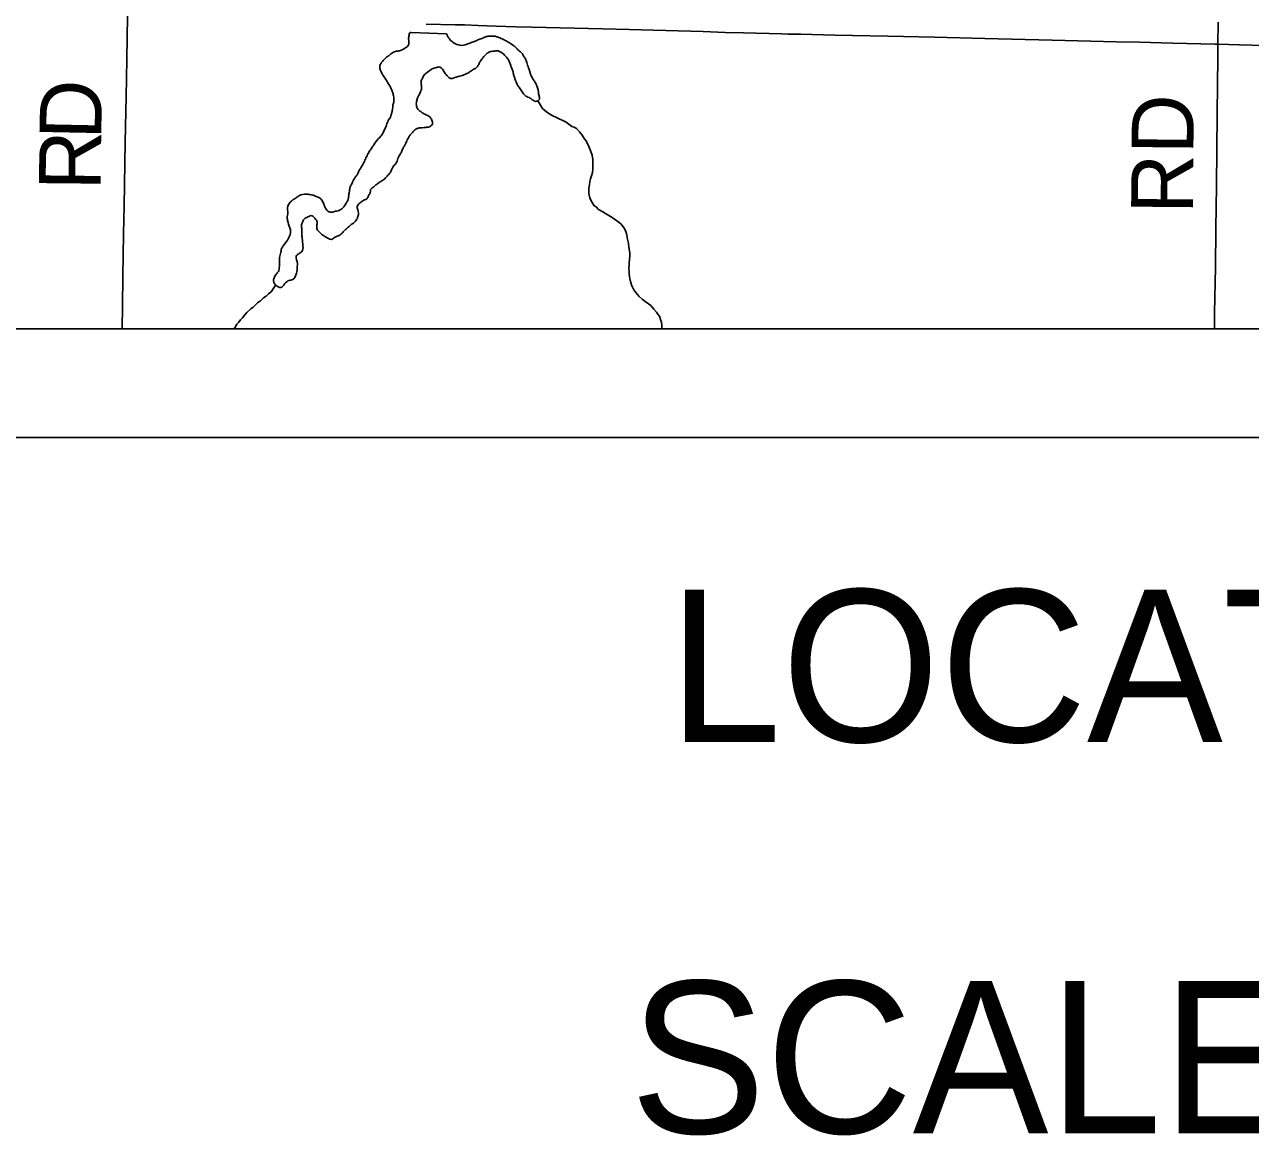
# Model space of a CAD drawing. Extents: x 0 to 34, y 0 to 22.
# Drawn here: x 25.659 to 26.787, y 13.358 to 14.38 of the extents above; entities that cross this region are included whole.
import ezdxf

# ---------------------------------------------------------------- set-up
doc = ezdxf.new("R2010")
doc.units = 0
for name, color, linetype in [('GM_X_County_Road', 7, 'Continuous'), ('GM_X_County_Road_Text', 7, 'Continuous'), ('GM_X_Minor_Lake', 7, 'Continuous'), ('GM_X_Minor_River', 7, 'Continuous'), ('GM_X_Township_Road', 7, 'Continuous'), ('SH_Data', 7, 'Continuous'), ('SH_Text', 7, 'Continuous')]:
    doc.layers.add(name, color=color, linetype=linetype)

msp = doc.modelspace()

# ---------------------------------------------------------------- linework, layer by layer
at = {"layer": 'GM_X_County_Road'}
for points in [[(25.7492, 14.1), (25.7496, 14.1206), (25.75, 14.1479), (25.7505, 14.1871), (25.7511, 14.2131), (25.7519, 14.2716), (25.7522, 14.2853), (25.7525, 14.3002), (25.7528, 14.3132), (25.7535, 14.3474), (25.7541, 14.3873)], [(26.7567, 14.3615), (26.7568, 14.3819)], [(26.7534, 14.1), (26.7536, 14.1147), (26.7543, 14.1563), (26.7548, 14.1917), (26.7553, 14.2315), (26.7559, 14.298), (26.7566, 14.3496), (26.7567, 14.3615)]]:
    msp.add_lwpolyline(points, dxfattribs=at)
at = {"layer": 'GM_X_Minor_Lake'}
msp.add_line((26.0475, 14.3712), (26.0148, 14.3725), dxfattribs=at)
for points in [[(26.0148, 14.3725), (26.0146, 14.3725), (26.013, 14.3699), (26.0126, 14.3664), (26.0129, 14.363), (26.0116, 14.3596), (26.0078, 14.3571), (26.0043, 14.3556), (26.0005, 14.355), (25.997, 14.3532), (25.9943, 14.351), (25.9916, 14.3491), (25.9892, 14.3465), (25.9869, 14.3436), (25.986, 14.3402), (25.9871, 14.3367), (25.9889, 14.3333), (25.9925, 14.3278), (25.9944, 14.3247), (25.9973, 14.3193), (25.9983, 14.3159), (25.999, 14.3121), (25.9989, 14.3083), (25.998, 14.3049), (25.9979, 14.3022), (25.9971, 14.2988), (25.9963, 14.2958), (25.9939, 14.2913), (25.9922, 14.2872), (25.991, 14.2842), (25.9894, 14.2808), (25.9874, 14.2774), (25.9847, 14.2745), (25.9807, 14.2692), (25.9787, 14.2663), (25.9764, 14.2629), (25.9744, 14.2591), (25.9724, 14.255), (25.9703, 14.2505), (25.9676, 14.2464), (25.9663, 14.2434), (25.9648, 14.2408), (25.9628, 14.2382), (25.9608, 14.234), (25.9592, 14.2311), (25.9583, 14.2277), (25.9579, 14.225), (25.9574, 14.2216), (25.9569, 14.2186), (25.9553, 14.2156), (25.953, 14.2122), (25.9491, 14.2089), (25.9464, 14.2082), (25.9426, 14.2072)], [(26.014, 14.2782), (26.0164, 14.2808), (26.0191, 14.2834), (26.0218, 14.2845), (26.0252, 14.2848), (26.0283, 14.2851), (26.0317, 14.2857), (26.0345, 14.2883), (26.0338, 14.2918), (26.0323, 14.2945), (26.0294, 14.2964), (26.0267, 14.2977), (26.0237, 14.2996), (26.0211, 14.302), (26.0197, 14.3054), (26.0198, 14.3081), (26.0206, 14.3115), (26.0218, 14.3141), (26.0234, 14.3175), (26.0243, 14.3201), (26.0244, 14.3236), (26.0241, 14.327), (26.0253, 14.3304), (26.0273, 14.3337), (26.03, 14.3359), (26.0343, 14.3389), (26.0381, 14.3403), (26.0412, 14.3406), (26.0438, 14.3386), (26.0456, 14.3355), (26.0486, 14.332), (26.0512, 14.3301), (26.0542, 14.3307), (26.0581, 14.3318), (26.0607, 14.3325), (26.0661, 14.3346), (26.0696, 14.3368), (26.0723, 14.3386), (26.0754, 14.3404), (26.077, 14.3431), (26.0786, 14.3461), (26.0806, 14.3487), (26.0829, 14.3516), (26.0856, 14.3538), (26.0883, 14.3549), (26.091, 14.3552), (26.0948, 14.3555), (26.0974, 14.3543), (26.1001, 14.3523), (26.1026, 14.3496), (26.1048, 14.3465), (26.107, 14.3404), (26.1084, 14.3369), (26.1091, 14.3335), (26.1101, 14.3304), (26.1112, 14.3277), (26.1123, 14.3246), (26.1145, 14.3215), (26.1196, 14.3145), (26.1233, 14.3125), (26.1263, 14.3106), (26.1293, 14.309), (26.1328, 14.3112), (26.1325, 14.3142), (26.1319, 14.318), (26.1312, 14.3215), (26.1298, 14.3249), (26.1283, 14.3276), (26.1265, 14.3303), (26.125, 14.3334), (26.124, 14.3365), (26.1229, 14.3399), (26.1212, 14.3449), (26.1201, 14.348), (26.1183, 14.3507), (26.1168, 14.3534), (26.1138, 14.3557), (26.1109, 14.3589), (26.1083, 14.3608), (26.1042, 14.3636), (26.1004, 14.3656), (26.0978, 14.3668), (26.0948, 14.368), (26.0921, 14.3689), (26.0887, 14.369), (26.0857, 14.369), (26.0826, 14.368), (26.0791, 14.3666), (26.0753, 14.3651), (26.0711, 14.3634), (26.068, 14.3623), (26.0645, 14.3609), (26.0584, 14.361), (26.0532, 14.3635), (26.0506, 14.3658), (26.0488, 14.3685), (26.0475, 14.3712)], [(25.9426, 14.2072), (25.9392, 14.2076), (25.9362, 14.2108), (25.9351, 14.2135), (25.9333, 14.2173), (25.9307, 14.2204), (25.9277, 14.2216), (25.9243, 14.2229), (25.9217, 14.2233), (25.9183, 14.2238), (25.9122, 14.2224), (25.9094, 14.2206), (25.9063, 14.2184), (25.9036, 14.2162), (25.9016, 14.2128), (25.9014, 14.2056), (25.901, 14.203), (25.9013, 14.1995), (25.9034, 14.1926), (25.9041, 14.1892), (25.9036, 14.1866), (25.8976, 14.1765), (25.8957, 14.1735), (25.8952, 14.1704), (25.8944, 14.1678), (25.8939, 14.1633), (25.8937, 14.156), (25.8932, 14.1534), (25.8913, 14.1508), (25.8893, 14.1474), (25.8884, 14.1444), (25.8891, 14.1417), (25.8917, 14.139), (25.8951, 14.1378), (25.8986, 14.1411), (25.9029, 14.1444), (25.9059, 14.1451), (25.9083, 14.1477), (25.9095, 14.151), (25.91, 14.1537), (25.9101, 14.1571), (25.9105, 14.1598), (25.9092, 14.1666), (25.9119, 14.1692), (25.915, 14.1718), (25.9155, 14.1745), (25.9149, 14.1813), (25.9146, 14.1844), (25.9143, 14.1878), (25.9144, 14.1912), (25.9141, 14.1946), (25.9149, 14.198), (25.9165, 14.2006), (25.92, 14.2028), (25.9238, 14.2039), (25.9264, 14.2015), (25.9286, 14.198), (25.9282, 14.1946), (25.9285, 14.1912), (25.931, 14.1885), (25.9336, 14.1861), (25.9363, 14.1845), (25.9415, 14.1821), (25.9442, 14.1836), (25.9469, 14.185), (25.9504, 14.1868), (25.9531, 14.1898), (25.9562, 14.1924), (25.9598, 14.1957), (25.9625, 14.1975), (25.9648, 14.2005), (25.966, 14.2031), (25.9665, 14.2065), (25.9658, 14.2092), (25.9655, 14.213), (25.9679, 14.2156), (25.9714, 14.2182), (25.9741, 14.2193), (25.9757, 14.2222), (25.9773, 14.2252), (25.9777, 14.2279), (25.9805, 14.2305), (25.9832, 14.2327), (25.9863, 14.2349), (25.9898, 14.2371), (25.9929, 14.2404), (25.9956, 14.2434), (25.9981, 14.2486), (26.0008, 14.252), (26.0028, 14.2565), (26.004, 14.2591), (26.0056, 14.2617), (26.0072, 14.2655), (26.0088, 14.2681), (26.0104, 14.2715), (26.0125, 14.2756), (26.014, 14.2782)]]:
    msp.add_spline(points, degree=3, dxfattribs=at)
at = {"layer": 'GM_X_Minor_River'}
for points in [[(26.1312, 14.3101), (26.1357, 14.3025), (26.1395, 14.2994), (26.1424, 14.2974), (26.1451, 14.2957), (26.1484, 14.2941), (26.1574, 14.29), (26.16, 14.288), (26.1626, 14.286), (26.1649, 14.2852), (26.1668, 14.284), (26.1697, 14.2809), (26.1723, 14.2781), (26.1741, 14.275), (26.1756, 14.273), (26.1777, 14.2692), (26.1788, 14.2661), (26.1802, 14.263), (26.1812, 14.2595), (26.1819, 14.2557), (26.1821, 14.2511), (26.1819, 14.2466), (26.1815, 14.2436), (26.1806, 14.2405), (26.1798, 14.2379), (26.1793, 14.2353), (26.1788, 14.2322), (26.1783, 14.2292), (26.1782, 14.2243), (26.1792, 14.2204), (26.1803, 14.2177), (26.1832, 14.2131), (26.185, 14.2119), (26.1872, 14.2095), (26.191, 14.2075), (26.1951, 14.2051), (26.1996, 14.2023), (26.204, 14.1991), (26.2078, 14.1963), (26.21, 14.1935), (26.2118, 14.1908), (26.2128, 14.1874), (26.2138, 14.1824), (26.2148, 14.1785), (26.2151, 14.1751), (26.2157, 14.1717), (26.216, 14.1694), (26.216, 14.1671), (26.2154, 14.1603), (26.2153, 14.1584), (26.2152, 14.1557), (26.2155, 14.1526), (26.2154, 14.15), (26.2157, 14.1481), (26.2161, 14.1462), (26.2167, 14.1435), (26.2177, 14.1393), (26.2195, 14.1358), (26.2214, 14.1334), (26.2247, 14.1295), (26.2273, 14.1271), (26.2302, 14.1251), (26.2332, 14.1228), (26.2354, 14.1212), (26.238, 14.118), (26.2406, 14.1153), (26.2417, 14.1134), (26.2431, 14.1114), (26.2442, 14.1083), (26.2452, 14.106), (26.2455, 14.1033), (26.2455, 14.1007), (26.2455, 14.1)], [(25.8905, 14.1403), (25.8862, 14.1338), (25.8839, 14.132), (25.8815, 14.1298), (25.8792, 14.1284), (25.8761, 14.1254), (25.8741, 14.124), (25.8722, 14.1221), (25.8698, 14.1199), (25.8675, 14.1181), (25.8639, 14.1148), (25.8619, 14.1126), (25.86, 14.11), (25.858, 14.1081), (25.8564, 14.1059), (25.8548, 14.1041), (25.8528, 14.1007), (25.8523, 14.1)]]:
    msp.add_lwpolyline(points, dxfattribs=at)
at = {"layer": 'GM_X_Township_Road'}
for points in [[(23.5167, 18.4074), (23.5167, 14.1), (28.7673, 14.1), (28.7709, 14.3107), (28.7934, 15.3155), (28.8021, 16.3696)], [(26.0287, 14.3801), (26.0554, 14.3795), (26.0641, 14.3793), (26.0765, 14.3788), (26.0845, 14.3785), (26.0932, 14.3782), (26.1113, 14.3776), (26.1262, 14.3774), (26.1519, 14.3767), (26.1911, 14.3756), (26.2154, 14.3751), (26.249, 14.3743), (26.2834, 14.3732), (26.3036, 14.3725), (26.3204, 14.372), (26.3557, 14.371), (26.3613, 14.3709), (26.3731, 14.3707), (26.4044, 14.37), (26.4533, 14.369), (26.4962, 14.368), (26.5422, 14.3669), (26.6043, 14.3654), (26.6634, 14.3639), (26.6845, 14.3634), (26.715, 14.3627), (26.7541, 14.3616), (26.7567, 14.3615)], [(26.7567, 14.3615), (26.7765, 14.3611), (26.7995, 14.3604), (26.8772, 14.3583), (26.9319, 14.3569), (27.0114, 14.3549), (27.0574, 14.354), (27.1463, 14.3523), (27.1923, 14.3514), (27.2526, 14.3503), (27.2595, 14.3502)]]:
    msp.add_lwpolyline(points, dxfattribs=at)
at = {"layer": 'SH_Data'}
for points in [[(23.4167, 21), (30.4167, 21), (30.4167, 14), (23.4167, 14)], [(23.5167, 20.9), (30.3167, 20.9), (30.3167, 14.1), (23.5167, 14.1)]]:
    msp.add_lwpolyline(points, close=True, dxfattribs=at)

# ---------------------------------------------------------------- texts
at = {"layer": 'GM_X_County_Road_Text'}
for s, height, rotation, p in [('D', 0.0568, 88.8597, (25.7299, 14.2736)), ('RD', 0.05682, 89.5063, (26.7336, 14.2055)), ('R', 0.0568, 89.4399, (25.7295, 14.2271))]:
    msp.add_text(s, height=height, rotation=rotation, dxfattribs=at).set_placement(p)
at = {"layer": 'SH_Text'}
for s, p in [('LOCATION MAP', (26.2513, 13.72)), ('SCALE IN MILES', (26.216, 13.36))]:
    msp.add_text(s, height=0.14, dxfattribs=at).set_placement(p)

doc.saveas('drawing.dxf')
